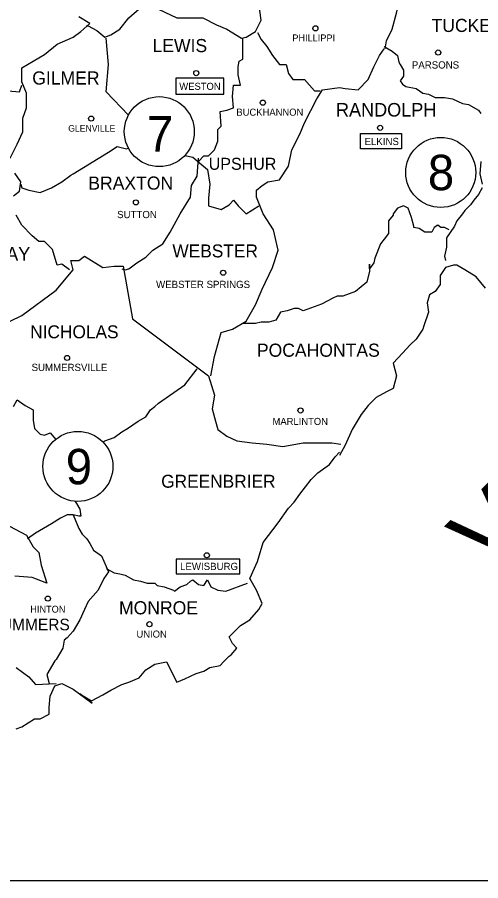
# Model space of a CAD drawing. Extents: x -2.1 to 5.9, y -23.5 to -12.8.
# Drawn here: x 3.484 to 4.174, y -23.135 to -21.85 of the extents above; entities that cross this region are included whole.
import ezdxf

# ---------------------------------------------------------------- set-up
doc = ezdxf.new("R2010")
doc.units = 0
doc.layers.add('Construction Line', color=7, linetype='Continuous')

msp = doc.modelspace()

# ---------------------------------------------------------------- linework, layer by layer
at = {"layer": 'Construction Line'}
msp.add_line((5.62, -23.1348), (-1.8802, -23.1348), dxfattribs=at)
for points in [[(4.0315, -21.8967), (4.0332, -21.8848), (4.0417, -21.8678), (4.0482, -21.844), (4.0536, -21.8205), (4.057, -21.8134), (4.0587, -21.7964), (4.0788, -21.7913), (4.089, -21.7882), (4.1026, -21.7814), (4.1267, -21.7882), (4.1366, -21.7913), (4.1485, -21.7933), (4.1567, -21.8049), (4.1669, -21.8151), (4.1808, -21.8273), (4.2029, -21.8273)], [(3.6853, -21.8338), (3.7213, -21.8508), (3.7414, -21.8508), (3.7598, -21.8508), (3.7805, -21.861), (3.7958, -21.8678), (3.8176, -21.8811), (3.8247, -21.8794), (3.8383, -21.8712), (3.8468, -21.8542), (3.8431, -21.829)], [(3.5862, -21.8627), (3.589, -21.8627), (3.6023, -21.8695), (3.6142, -21.8794), (3.6227, -21.876), (3.6363, -21.8678), (3.6496, -21.8508), (3.6652, -21.8372)], [(3.4731, -22.0596), (3.4836, -22.0389), (3.4921, -22.0205), (3.4921, -22.0001), (3.4972, -21.9848), (3.4972, -21.9627), (3.4904, -21.946), (3.4904, -21.9253), (3.5241, -21.9052), (3.5431, -21.8899), (3.5666, -21.8794), (3.5785, -21.8712), (3.5918, -21.8593), (3.5751, -21.8491)], [(3.649, -21.9956), (3.6159, -21.961), (3.6193, -21.9202), (3.6159, -21.8811)], [(3.7533, -22.0647), (3.7615, -22.0562), (3.7686, -22.0562), (3.7771, -22.0474), (3.7822, -22.0341), (3.7822, -22.0171), (3.7873, -22.012), (3.7856, -21.9902), (3.7958, -21.9882), (3.8057, -21.9848), (3.8043, -21.9678), (3.8057, -21.9511), (3.8159, -21.9511), (3.8125, -21.9355), (3.8125, -21.9236), (3.8142, -21.9151), (3.8193, -21.912), (3.8193, -21.8811)], [(3.8414, -21.8726), (3.8468, -21.8831), (3.855, -21.8933), (3.8635, -21.9069), (3.874, -21.9202), (3.8839, -21.9202), (3.8873, -21.9338), (3.8941, -21.9426), (3.9111, -21.9426), (3.9261, -21.9593), (3.9346, -21.9593)], [(3.3063, -21.9064), (3.3156, -21.8984), (3.3377, -21.8882), (3.3428, -21.8848), (3.353, -21.8831), (3.3666, -21.8882), (3.3734, -21.9001), (3.3819, -21.9001), (3.3938, -21.9018), (3.3921, -21.9253), (3.3938, -21.9426), (3.4003, -21.946), (3.4227, -21.9426), (3.4363, -21.9375), (3.453, -21.9559), (3.4615, -21.9593), (3.47, -21.9593), (3.487, -21.961), (3.4904, -21.9511)], [(4.0298, -21.8933), (4.0417, -21.9001), (4.0499, -21.9069), (4.0516, -21.9168), (4.0536, -21.9202), (4.0587, -21.9287), (4.0587, -21.9375), (4.0536, -21.9443), (4.057, -21.9494), (4.0621, -21.9528), (4.0774, -21.9559), (4.0873, -21.9627), (4.0958, -21.9644), (4.106, -21.9695), (4.1199, -21.9695), (4.1315, -21.9712), (4.1468, -21.978), (4.1553, -21.9797), (4.1706, -21.9882), (4.174, -21.993)], [(3.772, -22.3834), (3.7771, -22.3548), (3.7873, -22.3191), (3.8043, -22.314), (3.8247, -22.3021), (3.8383, -22.278), (3.8482, -22.2545), (3.8635, -22.2222), (3.872, -22.1967), (3.8652, -22.1661), (3.8499, -22.1426), (3.84, -22.1174), (3.84, -22.1072), (3.8482, -22.1001), (3.8567, -22.095), (3.874, -22.0916), (3.8873, -22.0715), (3.8924, -22.0474), (3.9043, -22.0239), (3.9111, -22.0069), (3.9295, -21.9712), (3.9383, -21.9579), (3.9635, -21.9545), (3.972, -21.9559), (3.991, -21.9579), (4.006, -21.9426), (4.0145, -21.9236), (4.023, -21.9069), (4.0298, -21.8967)], [(3.4887, -22.0984), (3.4904, -22.1035), (3.5006, -22.1072), (3.5176, -22.1106), (3.5346, -22.1035), (3.5499, -22.095), (3.5632, -22.0848), (3.5666, -22.0831), (3.6193, -22.0508), (3.6326, -22.0423), (3.6462, -22.0457), (3.6488, -22.0449)], [(3.6394, -22.2242), (3.6445, -22.2259), (3.6496, -22.2242), (3.6618, -22.2154), (3.6751, -22.2069), (3.6853, -22.1967), (3.7006, -22.1868), (3.7111, -22.1698), (3.7261, -22.1426), (3.7414, -22.1174), (3.7431, -22.1001), (3.7513, -22.0865), (3.7533, -22.0596)], [(3.7332, -22.0554), (3.7448, -22.0579), (3.755, -22.0664), (3.7669, -22.0766), (3.7703, -22.0984), (3.7686, -22.1191), (3.7686, -22.1307), (3.7873, -22.1358), (3.7992, -22.129), (3.8057, -22.1222), (3.8125, -22.1307), (3.8247, -22.1426), (3.8431, -22.1307)], [(4.174, -22.0647), (4.1723, -22.0831), (4.1757, -22.0984)], [(3.4782, -22.1157), (3.487, -22.1089), (3.4887, -22.095), (3.4802, -22.0817)], [(4.1757, -22.1035), (4.1706, -22.1134), (4.1635, -22.1222), (4.1584, -22.129), (4.1502, -22.1375), (4.1468, -22.1426), (4.1383, -22.1528), (4.1349, -22.161), (4.123, -22.1783), (4.123, -22.1834), (4.123, -22.1919), (4.1199, -22.2052), (4.1213, -22.212)], [(4.1267, -22.1661), (4.1199, -22.1627), (4.1142, -22.1627), (4.1097, -22.1593), (4.1043, -22.1627), (4.1009, -22.1698), (4.0907, -22.1698), (4.0822, -22.1644), (4.074, -22.1627), (4.074, -22.161), (4.0706, -22.1477), (4.0655, -22.1341), (4.0587, -22.1307), (4.0499, -22.1341), (4.0431, -22.1426), (4.0431, -22.1443), (4.0366, -22.1528), (4.0366, -22.1715), (4.0298, -22.18), (4.0247, -22.1868), (4.0162, -22.2086), (4.0145, -22.2154), (4.008, -22.2242), (4.008, -22.2171), (4.008, -22.2276), (4.0043, -22.2443), (3.9873, -22.2579), (3.9686, -22.2647), (3.9601, -22.2647), (3.9536, -22.2681), (3.9366, -22.2769), (3.9094, -22.2868), (3.9026, -22.2831), (3.8958, -22.2831), (3.8856, -22.2868), (3.8757, -22.2885), (3.8686, -22.3004), (3.8584, -22.3038), (3.8468, -22.3038), (3.8383, -22.3055), (3.8193, -22.3055)], [(3.5615, -22.2259), (3.5499, -22.2171), (3.5431, -22.2188), (3.5363, -22.1953), (3.5241, -22.1834), (3.5156, -22.1834), (3.5057, -22.1749), (3.4904, -22.1593), (3.4819, -22.1443)], [(3.4731, -22.3021), (3.4904, -22.2936), (3.5414, -22.2562), (3.5666, -22.2259), (3.5632, -22.212), (3.5751, -22.212), (3.5836, -22.2052), (3.6108, -22.2222), (3.6278, -22.2205), (3.6411, -22.2205), (3.655, -22.2987), (3.7686, -22.3834), (3.7771, -22.4123), (3.7737, -22.4327), (3.7788, -22.4511), (3.7822, -22.4633), (3.7958, -22.4735), (3.8108, -22.4803), (3.8332, -22.4834), (3.855, -22.4851), (3.8791, -22.4885), (3.9094, -22.4834), (3.9519, -22.4834), (3.9655, -22.4851)], [(4.1808, -22.2528), (4.1669, -22.2361), (4.1502, -22.2259), (4.1383, -22.2188), (4.1332, -22.2188), (4.1213, -22.2222), (4.1131, -22.2344), (4.1131, -22.2477), (4.106, -22.2579), (4.0975, -22.263), (4.0941, -22.2749), (4.0958, -22.2885), (4.089, -22.3089), (4.0873, -22.314), (4.0774, -22.329), (4.0689, -22.3375), (4.057, -22.3497), (4.0431, -22.3647), (4.0482, -22.3834), (4.0431, -22.4021), (4.0332, -22.4072), (4.0179, -22.4157), (4.006, -22.4276), (3.9955, -22.4409), (3.9822, -22.4633), (3.972, -22.4868), (3.9635, -22.5021)], [(3.6116, -22.4829), (3.6142, -22.4803), (3.6278, -22.4752), (3.6394, -22.4667), (3.6479, -22.4616), (3.6635, -22.4511), (3.6751, -22.4443), (3.6819, -22.4341), (3.6887, -22.4293), (3.6938, -22.4242), (3.7329, -22.3967), (3.7513, -22.3732)], [(3.4782, -22.4293), (3.4836, -22.4191), (3.4955, -22.4276), (3.5074, -22.4341), (3.5074, -22.4378), (3.5074, -22.4494), (3.5091, -22.4616), (3.5176, -22.4701), (3.5241, -22.4718), (3.5326, -22.4684), (3.5408, -22.478)], [(3.4819, -22.9089), (3.4904, -22.9058), (3.5091, -22.8939), (3.5176, -22.8939), (3.5309, -22.8871), (3.5309, -22.8769), (3.5326, -22.8602), (3.5397, -22.8446), (3.5499, -22.8412), (3.5666, -22.8497), (3.5952, -22.8704), (3.5768, -22.8565), (3.5941, -22.867), (3.6108, -22.8582), (3.6227, -22.8514), (3.6394, -22.8429), (3.6496, -22.8395), (3.6652, -22.8327), (3.6751, -22.8211), (3.6887, -22.8126), (3.706, -22.8092), (3.7213, -22.8395), (3.7329, -22.8344), (3.7499, -22.8262), (3.7615, -22.8228), (3.7703, -22.8177), (3.7856, -22.8143), (3.7907, -22.8092), (3.7992, -22.8004), (3.8023, -22.7987), (3.8108, -22.7888), (3.8043, -22.782), (3.7992, -22.7718), (3.8074, -22.7633), (3.8159, -22.7551), (3.8298, -22.7466), (3.8431, -22.731), (3.8482, -22.7225), (3.84, -22.7024), (3.8298, -22.6851), (3.8414, -22.6599), (3.8499, -22.6313), (3.872, -22.6021), (3.8873, -22.5803), (3.8958, -22.5715), (3.9043, -22.5596), (3.921, -22.5378), (3.9312, -22.5276), (3.9485, -22.5154), (3.957, -22.5038), (3.9635, -22.497)], [(3.57, -22.5704), (3.5717, -22.5735), (3.5768, -22.582), (3.5785, -22.5922), (3.5751, -22.5922), (3.5666, -22.5905), (3.5751, -22.6106), (3.5802, -22.6191), (3.5873, -22.6262), (3.5918, -22.633), (3.5972, -22.6429), (3.6091, -22.6514), (3.6193, -22.6752), (3.6125, -22.6851), (3.604, -22.7024), (3.589, -22.7191), (3.5836, -22.731), (3.5768, -22.7466), (3.5666, -22.7633), (3.5581, -22.7735), (3.5533, -22.7769), (3.5516, -22.7888), (3.5414, -22.8058), (3.5397, -22.8075), (3.5275, -22.8279), (3.5309, -22.8412)], [(3.5666, -22.5905), (3.5581, -22.5905), (3.5482, -22.5953), (3.5346, -22.6038), (3.5108, -22.6174), (3.4989, -22.6262)], [(3.472, -22.6072), (3.4972, -22.6208), (3.5074, -22.6378), (3.5156, -22.6463), (3.519, -22.665), (3.5275, -22.6922), (3.5057, -22.6834), (3.4802, -22.6817)], [(3.6159, -22.6701), (3.6278, -22.6766), (3.6363, -22.6783), (3.6445, -22.68), (3.6567, -22.6868), (3.6669, -22.6888), (3.6768, -22.6922), (3.6887, -22.6922), (3.6921, -22.6956), (3.7023, -22.6973), (3.7162, -22.7024), (3.7176, -22.7041), (3.7261, -22.6973), (3.7363, -22.6939), (3.7414, -22.6888), (3.7448, -22.6868), (3.7533, -22.6939), (3.7615, -22.6956), (3.7669, -22.6868), (3.772, -22.6973), (3.7822, -22.7024), (3.7941, -22.7041), (3.8264, -22.6922)], [(3.4819, -22.8177), (3.5006, -22.8313), (3.5108, -22.8429), (3.5414, -22.8412)]]:
    msp.add_lwpolyline(points, dxfattribs=at)
for points in [[(3.7199, -21.9406), (3.7199, -21.9644), (3.7913, -21.9644), (3.7913, -21.9406)], [(3.9947, -22.0231), (4.0556, -22.0231), (4.0556, -22.0455), (3.9947, -22.0455)], [(3.8151, -22.6562), (3.7204, -22.6562), (3.7204, -22.6783), (3.8151, -22.6783)]]:
    msp.add_lwpolyline(points, close=True, dxfattribs=at)
for centre, radius in [((3.9276, -21.8664), 0.00381), ((4.1104, -21.9024), 0.00381), ((3.7501, -21.933), 0.00381), ((3.6951, -22.0201), 0.0521), ((3.8493, -21.977), 0.00381), ((3.5937, -22.0007), 0.00381), ((4.0238, -22.0144), 0.00381), ((4.1142, -22.0808), 0.0521), ((3.6603, -22.1254), 0.00381), ((3.7902, -22.23), 0.00381), ((3.5577, -22.3568), 0.00381), ((3.9054, -22.435), 0.00381), ((3.5739, -22.5182), 0.0521), ((3.7659, -22.6505), 0.00381), ((3.5292, -22.715), 0.00381), ((3.6803, -22.7531), 0.00381)]:
    msp.add_circle(centre, radius, dxfattribs=at)

# ---------------------------------------------------------------- texts
for s, height, p in [('TUCKER', 0.01955, (4.1005, -21.8718)), ('LEWIS', 0.01955, (3.685, -21.9018)), ('PHILLIPPI', 0.0102, (3.8932, -21.8857)), ('PARSONS', 0.01076, (4.0712, -21.9262)), ('GILMER', 0.01955, (3.5059, -21.95)), ('WESTON', 0.01048, (3.7249, -21.9579)), ('RANDOLPH', 0.02011, (3.9582, -21.9976)), ('7', 0.0527, (3.6768, -22.0497)), ('BUCKHANNON', 0.01048, (3.8099, -21.9964)), ('GLENVILLE', 0.00963, (3.5595, -22.02)), ('ELKINS', 0.01076, (4.0007, -22.0401)), ('UPSHUR', 0.01785, (3.7687, -22.0769)), ('8', 0.0527, (4.095, -22.1072)), ('BRAXTON', 0.01955, (3.5894, -22.1064)), ('SUTTON', 0.01076, (3.6323, -22.1488)), ('WEBSTER', 0.01926, (3.7146, -22.2072)), ('CLAY', 0.02011, (3.4327, -22.212)), ('WEBSTER SPRINGS', 0.010765, (3.6903, -22.2528)), ('NICHOLAS', 0.01926, (3.5028, -22.3276)), ('POCAHONTAS', 0.01955, (3.8404, -22.3551)), ('SUMMERSVILLE', 0.010765, (3.5049, -22.3763)), ('MARLINTON', 0.01048, (3.8637, -22.4565)), ('9', 0.0527, (3.5558, -22.5449)), ('GREENBRIER', 0.01926, (3.6979, -22.55)), ('LEWISBURG', 0.01076, (3.726, -22.6724)), ('HINTON', 0.0102, (3.503, -22.7358)), ('MONROE', 0.01955, (3.6351, -22.7384)), ('SUMMERS', 0.01728, (3.4437, -22.7622)), ('UNION', 0.01048, (3.6611, -22.773))]:
    msp.add_text(s, height=height, dxfattribs=at).set_placement(p)
msp.add_text('VIRGINIA', height=0.10497, rotation=45, dxfattribs=at).set_placement((4.1927, -22.6823))

doc.saveas('drawing.dxf')
